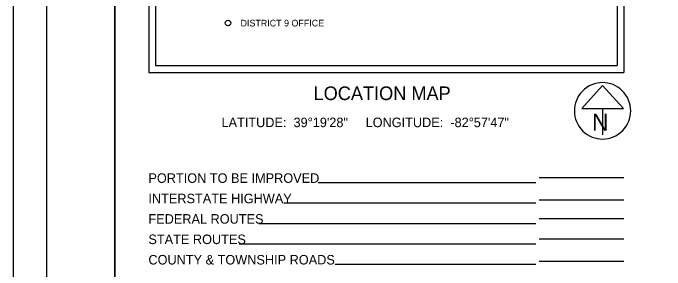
# Model space of a CAD drawing. Extents: x 0 to 34, y 0 to 22.
# Drawn here: x 0 to 9.6, y 11.1 to 14.87 of the extents above; entities that cross this region are included whole.
import ezdxf

# ---------------------------------------------------------------- set-up
doc = ezdxf.new("R2010")
doc.units = 0
for name, color, linetype in [('Default', 7, 'Continuous'), ('SH_Border', 7, 'Continuous'), ('SH_Cut_Line', 7, 'Continuous'), ('SH_Data', 7, 'Continuous'), ('SH_Text', 7, 'Continuous')]:
    doc.layers.add(name, color=color, linetype=linetype)

msp = doc.modelspace()

# ---------------------------------------------------------------- linework, layer by layer
at = {"layer": 'Default'}
msp.add_circle((3.1673, 14.7271), 0.0411, dxfattribs=at)
at = {"layer": 'SH_Border'}
for points in [[(0.5, 21.5), (1.5, 21.5), (1.5, 0.5), (0.5, 0.5)], [(1.5, 21.5), (33.5, 21.5), (33.5, 0.5), (1.5, 0.5)]]:
    msp.add_lwpolyline(points, close=True, dxfattribs=at)
at = {"layer": 'SH_Cut_Line'}
msp.add_lwpolyline([(0, 0), (34, 0), (34, 22), (0, 22)], close=True, dxfattribs=at)
at = {"layer": 'SH_Data'}
for p, q in [((2, 21), (2, 14)), ((9, 21), (9, 14)), ((2.1, 20.9), (2.1, 14.1)), ((8.9, 20.9), (8.9, 14.1)), ((2.1, 14.1), (8.9, 14.1)), ((2.1, 14.1), (2.1, 14.1)), ((2, 14), (9, 14)), ((8.6845, 13.8091), (8.3769, 13.4678)), ((8.9921, 13.4678), (8.6845, 13.8091)), ((8.3769, 13.4678), (8.9921, 13.4678)), ((8.6845, 13.4678), (8.6845, 13.0811)), ((8.6845, 13.4353), (8.6845, 13.4353)), ((8.6845, 13.4353), (8.6845, 13.4353)), ((7.75, 12.4553), (9, 12.4553)), ((7.7, 12.3767), (4.4937, 12.3767)), ((9, 12.1207), (7.75, 12.1207)), ((7.7, 12.0767), (3.9895, 12.0767)), ((9, 11.8491), (7.75, 11.8491)), ((7.7, 11.7767), (3.6192, 11.7767)), ((9, 11.5491), (7.75, 11.5491)), ((7.7, 11.4767), (3.3288, 11.4767)), ((7.7, 11.1767), (4.7452, 11.1767)), ((9, 11.2223), (7.75, 11.2223))]:
    msp.add_line(p, q, dxfattribs=at)
msp.add_arc((8.6845, 13.4353), 0.4148, 129.77984, 129.76332, dxfattribs=at)

# ---------------------------------------------------------------- texts
at = {"layer": 'Default'}
msp.add_text('DISTRICT 9 OFFICE', height=0.098, dxfattribs=at).set_placement((3.3519, 14.6763))
at = {"layer": 'SH_Data'}
msp.add_text('N', height=0.25, dxfattribs=at).set_placement((8.5292, 13.144))
at = {"layer": 'SH_Text'}
for s, height, p in [('LOCATION MAP', 0.2, (4.4269, 13.5938)), ('LATITUDE:  39°19\'28"     LONGITUDE:  -82°57\'47"', 0.14, (3.071, 13.1959)), ('PORTION TO BE IMPROVED', 0.14, (1.9944, 12.3767)), ('INTERSTATE HIGHWAY', 0.14, (1.9944, 12.0767)), ('FEDERAL ROUTES', 0.14, (1.9944, 11.7767)), ('STATE ROUTES', 0.14, (1.9944, 11.4767)), ('COUNTY & TOWNSHIP ROADS', 0.14, (1.9944, 11.1767))]:
    msp.add_text(s, height=height, dxfattribs=at).set_placement(p)

doc.saveas('drawing.dxf')
